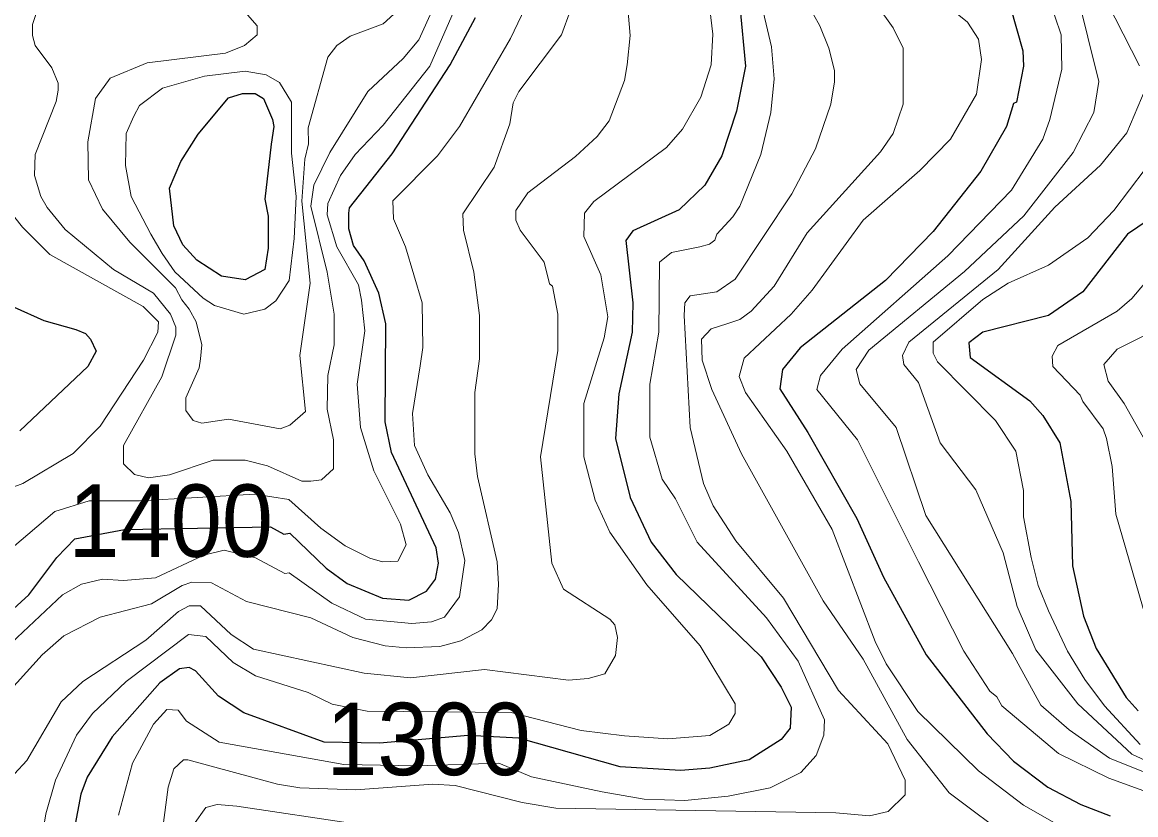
# Model space of a CAD drawing. Extents: x 423 to 448.8, y 7456.3 to 7484.
# Drawn here: x 434.869 to 436.1, y 7473.326 to 7474.202 of the extents above; entities that cross this region are included whole.
import ezdxf
from ezdxf.enums import TextEntityAlignment as Align

# ---------------------------------------------------------------- set-up
doc = ezdxf.new("R2010")
doc.units = 0
doc.header["$LTSCALE"] = 0.032
doc.layers.add('1', color=7, linetype='Continuous', lineweight=25)
doc.layers.add('2', color=7, linetype='Continuous', lineweight=13)
doc.layers.add('61', color=7, linetype='Continuous')

msp = doc.modelspace()

# ---------------------------------------------------------------- linework, layer by layer
at = {"layer": '1'}
for points in [[(435.6623, 7474.2194), (435.6685, 7474.1529), (435.6585, 7474.1034), (435.6422, 7474.0539), (435.6237, 7474.0214), (435.5951, 7473.9943), (435.544, 7473.9711), (435.5363, 7473.9603), (435.544, 7473.8915), (435.5432, 7473.859), (435.5285, 7473.7909), (435.5247, 7473.7414), (435.5409, 7473.6764), (435.5641, 7473.6269), (435.5919, 7473.5913), (435.6856, 7473.5001), (435.708, 7473.4668), (435.7188, 7473.4444), (435.718, 7473.4212), (435.708, 7473.4088), (435.6724, 7473.3864), (435.6291, 7473.3771), (435.5966, 7473.3747), (435.5301, 7473.3786)], [(435.9609, 7474.2194), (435.9748, 7474.1699), (435.9756, 7474.1529), (435.9679, 7474.1134), (435.9647, 7474.1119), (435.957, 7474.0864), (435.9284, 7474.0369), (435.8758, 7473.9703), (435.8232, 7473.9162), (435.7289, 7473.8419), (435.7095, 7473.8179), (435.7064, 7473.7963), (435.7374, 7473.7483), (435.7915, 7473.6532), (435.8209, 7473.5883), (435.8681, 7473.5024), (435.9354, 7473.415), (435.9648, 7473.3848), (436.0027, 7473.3562), (436.039, 7473.3369), (436.0715, 7473.3245)], [(434.8595, 7473.5534), (434.8765, 7473.5689), (434.9074, 7473.6099), (434.9272, 7473.6307), (434.982, 7473.641), (435.1436, 7473.6437), (435.1583, 7473.6358), (435.165, 7473.637), (435.2052, 7473.5983), (435.2284, 7473.5813), (435.2671, 7473.565), (435.2965, 7473.5627), (435.3158, 7473.5728), (435.3259, 7473.5859), (435.329, 7473.6037), (435.3266, 7473.6208), (435.2772, 7473.7259), (435.2702, 7473.76), (435.271, 7473.8683), (435.2632, 7473.9023), (435.247, 7473.9379), (435.2354, 7473.9549), (435.23, 7473.9734), (435.23, 7473.9905), (435.2307, 7473.9966), (435.2779, 7474.0562), (435.3421, 7474.1544), (435.37, 7474.207)], [(436.1705, 7474.0214), (436.0908, 7473.9672), (436.0413, 7473.9038), (436.0035, 7473.8775), (435.9308, 7473.859), (435.9153, 7473.8474), (435.9168, 7473.8311), (435.9826, 7473.7831), (435.9972, 7473.7669), (436.0158, 7473.7368), (436.0282, 7473.6718), (436.0297, 7473.6006), (436.0421, 7473.545), (436.056, 7473.5094), (436.0893, 7473.4552), (436.1024, 7473.4405)], [(434.8603, 7473.8868), (434.8928, 7473.8721), (434.9284, 7473.8621), (434.9391, 7473.8574), (434.9446, 7473.8512), (434.9507, 7473.838), (434.9415, 7473.8211), (434.8665, 7473.7499)], [(435.5301, 7473.3786), (435.4179, 7473.4104), (435.3621, 7473.4133), (435.264, 7473.4046), (435.2027, 7473.406), (435.114, 7473.4382), (435.0861, 7473.4568), (435.0606, 7473.4846), (435.0536, 7473.4884), (435.0428, 7473.4869), (435.0211, 7473.4714), (434.9686, 7473.4119), (434.9407, 7473.367), (434.9338, 7473.3485), (434.9229, 7473.2897), (434.9252, 7473.1892), (434.9229, 7473.1319), (434.9082, 7473.0886), (434.8812, 7473.0584), (434.8556, 7473.0383)]]:
    msp.add_lwpolyline(points, dxfattribs=at)
msp.add_lwpolyline([(435.0636, 7474.0778), (435.097, 7474.1181), (435.1124, 7474.1227), (435.1264, 7474.1227), (435.1356, 7474.1173), (435.1457, 7474.0941), (435.1472, 7474.0864), (435.1442, 7474.0668), (435.1372, 7474.0059), (435.141, 7473.9874), (435.141, 7473.9518), (435.1372, 7473.9285), (435.1155, 7473.9169), (435.0892, 7473.9208), (435.0621, 7473.9386), (435.0467, 7473.9556), (435.0366, 7473.9765), (435.032, 7474.0183), (435.0444, 7474.0477)], close=True, dxfattribs=at)
at = {"layer": '2'}
for points in [[(435.6701, 7474.2906), (435.6972, 7474.1745), (435.7003, 7474.139), (435.6964, 7474.1018), (435.6855, 7474.0554), (435.6623, 7473.9982), (435.6546, 7473.9866), (435.6368, 7473.9673), (435.6346, 7473.9606), (435.6288, 7473.9563), (435.6179, 7473.9534), (435.5865, 7473.9471), (435.5734, 7473.9363), (435.5726, 7473.859), (435.5626, 7473.8017), (435.5626, 7473.743), (435.5765, 7473.6965), (435.5912, 7473.6749), (435.6152, 7473.6269), (435.6917, 7473.5434), (435.7265, 7473.4954), (435.7559, 7473.4304), (435.7551, 7473.4135), (435.7466, 7473.391), (435.7297, 7473.3724), (435.6956, 7473.3554), (435.6492, 7473.3461), (435.6013, 7473.3415), (435.5564, 7473.343), (435.51, 7473.3508), (435.4318, 7473.3676), (435.3958, 7473.3826), (435.3057, 7473.3796), (435.2246, 7473.381), (435.0869, 7473.4057), (435.0506, 7473.4289), (435.0413, 7473.4413), (435.0289, 7473.4421), (435.0142, 7473.4258), (434.991, 7473.3825), (434.9755, 7473.3253)], [(434.8378, 7473.6037), (434.9051, 7473.661), (434.943, 7473.6725), (434.9986, 7473.6726), (435.1262, 7473.6801), (435.1637, 7473.6741), (435.199, 7473.6424), (435.2261, 7473.623), (435.2532, 7473.6091), (435.2671, 7473.6053), (435.2841, 7473.606), (435.2934, 7473.6238), (435.2872, 7473.647), (435.2578, 7473.7058), (435.2431, 7473.7538), (435.2393, 7473.8017), (435.2478, 7473.8605), (435.2439, 7473.8946), (435.2408, 7473.9115), (435.2168, 7473.9533), (435.206, 7473.9889), (435.2068, 7474.0013), (435.2207, 7474.0322), (435.237, 7474.0554), (435.2679, 7474.0879), (435.3197, 7474.1529), (435.3708, 7474.2705)], [(434.8448, 7473.5039), (434.9136, 7473.5689), (434.9345, 7473.5805), (434.9577, 7473.5859), (434.9809, 7473.5844), (435.0165, 7473.5875), (435.0698, 7473.6127), (435.0923, 7473.618), (435.1269, 7473.6097), (435.1592, 7473.5924), (435.1642, 7473.5929), (435.2114, 7473.5596), (435.2486, 7473.5419), (435.2996, 7473.5372), (435.3213, 7473.5388), (435.3359, 7473.5441), (435.3522, 7473.5666), (435.3584, 7473.6068), (435.3514, 7473.6377), (435.3421, 7473.6594), (435.3174, 7473.7012), (435.3027, 7473.7336), (435.3004, 7473.7693), (435.3089, 7473.8218), (435.312, 7473.842), (435.3112, 7473.8915), (435.2926, 7473.9533), (435.2795, 7473.9843), (435.2787, 7474.0044), (435.3282, 7474.0539), (435.3522, 7474.0863), (435.4087, 7474.1838), (435.4373, 7474.2442)], [(435.6268, 7474.2349), (435.6322, 7474.1885), (435.6306, 7474.1544), (435.619, 7474.1189), (435.5989, 7474.0833), (435.5811, 7474.0631), (435.5007, 7474.0036), (435.4906, 7473.9905), (435.4899, 7473.9649), (435.5084, 7473.9224), (435.5162, 7473.876), (435.5123, 7473.8528), (435.4899, 7473.7801), (435.4899, 7473.7213), (435.5023, 7473.6733), (435.5185, 7473.6378), (435.5595, 7473.5797), (435.6183, 7473.5125), (435.6569, 7473.4482), (435.6569, 7473.4374), (435.65, 7473.4258), (435.6291, 7473.4134), (435.5827, 7473.4096), (435.5347, 7473.4127), (435.4868, 7473.4188), (435.4096, 7473.4387), (435.2505, 7473.4403), (435.2115, 7473.4479), (435.1851, 7473.4606), (435.1271, 7473.4792), (435.1024, 7473.4939), (435.0722, 7473.5225), (435.0529, 7473.5248), (434.984, 7473.473), (434.9469, 7473.4374), (434.9291, 7473.4135), (434.9059, 7473.364), (434.8951, 7473.3268), (434.8912, 7473.3021)], [(435.0915, 7474.2403), (435.1286, 7474.1977), (435.1286, 7474.1877), (435.1147, 7474.176), (435.0939, 7474.1676), (435.0072, 7474.1567), (434.9662, 7474.1397), (434.95, 7474.1173), (434.9415, 7474.0694), (434.9422, 7474.0276), (434.9577, 7473.9951), (434.9879, 7473.9587), (435.0385, 7473.9082), (435.0455, 7473.8949), (435.0536, 7473.8845), (435.0614, 7473.8706), (435.0676, 7473.8451), (435.066, 7473.8296), (435.0645, 7473.8195), (435.0498, 7473.7863), (435.0498, 7473.7723), (435.0582, 7473.7615), (435.0676, 7473.7584), (435.097, 7473.763), (435.1542, 7473.7522), (435.165, 7473.7561), (435.182, 7473.7715), (435.1759, 7473.8334), (435.1874, 7473.9131), (435.1783, 7474.0039), (435.1813, 7474.0504), (435.1856, 7474.0674), (435.1851, 7474.0848), (435.2068, 7474.1629), (435.2168, 7474.176), (435.2315, 7474.1861), (435.2679, 7474.2), (435.288, 7474.2178)], [(436.0347, 7474.2345), (436.059, 7474.136), (436.0533, 7474.1018), (436.0305, 7474.0575), (435.9762, 7473.9876), (435.9106, 7473.9262), (435.8049, 7473.8391), (435.7907, 7473.8177), (435.7949, 7473.802), (435.8349, 7473.7535), (435.8677, 7473.6564), (435.9634, 7473.5037), (435.9948, 7473.4466), (436.0262, 7473.4195), (436.0709, 7473.3883), (436.144, 7473.3587)], [(436.0591, 7474.2418), (436.104, 7474.1536)], [(435.5378, 7474.1544), (435.5409, 7474.1869), (435.5378, 7474.2256)], [(435.7188, 7473.8791), (435.742, 7473.9053), (435.7985, 7473.9827), (435.8611, 7474.0376), (435.8951, 7474.0725), (435.9238, 7474.122), (435.9292, 7474.1606), (435.9261, 7474.183), (435.9137, 7474.2016), (435.8782, 7474.231)], [(436.0034, 7474.2294), (436.0174, 7474.1877), (436.0181, 7474.1498), (436.005, 7474.0941), (435.9972, 7474.0725), (435.9624, 7474.016), (435.8921, 7473.9433), (435.7753, 7473.8404), (435.7513, 7473.811), (435.7474, 7473.7956), (435.7923, 7473.7399), (435.8596, 7473.6053), (435.9098, 7473.5063), (435.9385, 7473.4622), (435.9462, 7473.456), (435.9516, 7473.4459), (436.0143, 7473.3933), (436.07, 7473.3662), (436.1288, 7473.3446)], [(434.8355, 7473.4413), (434.8912, 7473.5024), (434.9152, 7473.5233), (434.9554, 7473.5441), (435.0119, 7473.5589), (435.0459, 7473.579), (435.0567, 7473.5828), (435.0784, 7473.5821), (435.1171, 7473.5612), (435.1882, 7473.5434), (435.2346, 7473.5217), (435.2702, 7473.5124), (435.2934, 7473.5101), (435.3306, 7473.5117), (435.3538, 7473.5178), (435.3769, 7473.5302), (435.3878, 7473.5411), (435.394, 7473.5534), (435.3955, 7473.5805), (435.394, 7473.6053), (435.3723, 7473.6996), (435.3692, 7473.7244), (435.3692, 7473.7925), (435.3746, 7473.8296), (435.3746, 7473.8775), (435.3684, 7473.9255), (435.3568, 7473.9719), (435.356, 7473.9897), (435.3908, 7474.0415), (435.4079, 7474.0895), (435.4117, 7474.1127), (435.4179, 7474.125), (435.4651, 7474.1877), (435.4752, 7474.2148)], [(435.3236, 7474.2179), (435.3073, 7474.1823), (435.2903, 7474.1614), (435.2509, 7474.125), (435.2091, 7474.0577), (435.1913, 7474.0214), (435.1882, 7473.9982), (435.206, 7473.9255), (435.2137, 7473.8791), (435.2137, 7473.8451), (435.2068, 7473.811), (435.206, 7473.7739), (435.213, 7473.7399), (435.213, 7473.7081), (435.1998, 7473.6958), (435.1882, 7473.6942), (435.1782, 7473.6942), (435.1403, 7473.7112), (435.1155, 7473.7174), (435.08, 7473.7174), (435.032, 7473.7012), (435.0088, 7473.6981), (434.9933, 7473.7019), (434.9809, 7473.7135), (434.9809, 7473.7337), (435.0235, 7473.8095), (435.0389, 7473.8559), (435.0389, 7473.8644), (435.0328, 7473.8791), (435.0142, 7473.9022), (434.9701, 7473.9285), (434.9167, 7473.9727), (434.8966, 7473.9967), (434.8896, 7474.009), (434.8827, 7474.0322), (434.8835, 7474.0554), (434.9067, 7474.1142), (434.909, 7474.1266), (434.909, 7474.1343), (434.902, 7474.1513), (434.8835, 7474.1761), (434.8804, 7474.1869), (434.8804, 7474.1993), (434.885, 7474.2124)], [(435.7435, 7474.2101), (435.7505, 7474.1978), (435.7606, 7474.173), (435.7668, 7474.1483), (435.7668, 7474.1359), (435.7629, 7474.1111), (435.7459, 7474.0616), (435.7196, 7474.0121), (435.6569, 7473.9178), (435.6368, 7473.9038), (435.6074, 7473.8992), (435.6013, 7473.8914), (435.6005, 7473.8775), (435.6074, 7473.7538), (435.6221, 7473.6919), (435.6329, 7473.6672), (435.6577, 7473.6285), (435.7103, 7473.565), (435.7714, 7473.463), (435.8256, 7473.4041), (435.8449, 7473.364), (435.8449, 7473.3477), (435.8263, 7473.3291), (435.8055, 7473.3245), (435.7683, 7473.3276), (435.4589, 7473.333), (435.4218, 7473.3392), (435.3476, 7473.3578), (435.3228, 7473.3593), (435.2377, 7473.3531), (435.1759, 7473.3554), (435.1511, 7473.3593), (435.0521, 7473.3864), (435.0475, 7473.3864), (435.0366, 7473.3763), (435.0304, 7473.3562), (435.0188, 7473.2696)], [(435.8139, 7474.2202), (435.8317, 7474.1954)], [(435.8317, 7474.1954), (435.8426, 7474.173), (435.8426, 7474.1111), (435.8317, 7474.0786), (435.8178, 7474.0585), (435.7366, 7473.9688), (435.7002, 7473.91), (435.6747, 7473.8822), (435.6623, 7473.8729), (435.6477, 7473.8683), (435.6307, 7473.8628), (435.6198, 7473.8512), (435.6206, 7473.828), (435.6314, 7473.7956), (435.6639, 7473.7244), (435.7544, 7473.562), (435.7985, 7473.4977), (435.8472, 7473.4088), (435.8936, 7473.35), (435.9655, 7473.2959), (436.0189, 7473.2742), (436.0901, 7473.2549), (436.2138, 7473.2371)], [(434.8193, 7473.3268), (434.8742, 7473.3856), (434.9121, 7473.4506), (434.936, 7473.473), (435.0057, 7473.5186), (435.042, 7473.5503), (435.0536, 7473.5565), (435.066, 7473.5565), (435.1001, 7473.5248), (435.1248, 7473.5086), (435.247, 7473.4823), (435.2981, 7473.4768), (435.3801, 7473.4861), (435.4729, 7473.4745), (435.4945, 7473.4761), (435.513, 7473.4815), (435.5247, 7473.5016), (435.527, 7473.5217), (435.5239, 7473.5356), (435.5185, 7473.5418), (435.4674, 7473.5751), (435.4543, 7473.6037), (435.4419, 7473.7213), (435.4612, 7473.8389), (435.4612, 7473.8791), (435.455, 7473.91), (435.452, 7473.9123), (435.4458, 7473.9363), (435.4195, 7473.9719), (435.4148, 7473.9827), (435.4148, 7473.9936), (435.428, 7474.0129), (435.4806, 7474.0531), (435.5045, 7474.0755), (435.5177, 7474.0925), (435.5347, 7474.1374), (435.5378, 7474.1544)], [(436.1102, 7474.1273), (436.0901, 7474.0794), (436.0607, 7474.0438), (436.0104, 7473.9974), (435.9477, 7473.9285), (435.8488, 7473.8481), (435.8418, 7473.8334), (435.8433, 7473.8234), (435.8596, 7473.8033), (435.8836, 7473.7368), (435.923, 7473.6849), (435.9532, 7473.6153), (435.9686, 7473.5558), (435.9895, 7473.5078), (436.0359, 7473.4482), (436.0956, 7473.3925)], [(436.1102, 7474.0392), (436.0754, 7473.9936), (436.0467, 7473.9634), (436.0035, 7473.9332), (435.9586, 7473.9131), (435.9308, 7473.8953), (435.8758, 7473.8481), (435.8758, 7473.8358), (435.8805, 7473.8264), (435.9447, 7473.7615), (435.9671, 7473.7275), (435.9756, 7473.6842), (435.9756, 7473.6548), (435.9841, 7473.6099), (435.9918, 7473.579), (436.0035, 7473.5511), (436.0243, 7473.5063), (436.0436, 7473.4753), (436.0653, 7473.4459)], [(434.8525, 7473.9966), (434.8695, 7473.975), (434.8997, 7473.9448), (435.0026, 7473.8876), (435.0196, 7473.8706), (435.0188, 7473.859), (435.0033, 7473.828), (434.9554, 7473.7553), (434.9253, 7473.7251), (434.8696, 7473.6919), (434.7969, 7473.6648)], [(436.1574, 7473.9696), (436.0955, 7473.8961), (436.0792, 7473.8822), (436.0135, 7473.8443), (436.0073, 7473.8326), (436.0081, 7473.821), (436.0382, 7473.7893), (436.0413, 7473.7824), (436.0638, 7473.7522), (436.0676, 7473.7414), (436.0738, 7473.7105), (436.0777, 7473.6579), (436.1295, 7473.48)], [(436.1117, 7473.2765), (436.0127, 7473.3152), (435.9756, 7473.3361), (435.9261, 7473.374), (435.8588, 7473.4398), (435.824, 7473.4924), (435.8116, 7473.5171), (435.7644, 7473.6409), (435.7141, 7473.7275), (435.6685, 7473.7925), (435.6616, 7473.8102), (435.667, 7473.8303), (435.7188, 7473.8791)], [(436.1117, 7473.8566), (436.0793, 7473.8404), (436.0645, 7473.8234), (436.0692, 7473.8048), (436.087, 7473.7801), (436.1078, 7473.743)], [(436.0653, 7473.4459), (436.1048, 7473.4034)], [(436.0956, 7473.3925), (436.1424, 7473.3709)], [(435.2393, 7473.3152), (435.1062, 7473.3353), (435.0846, 7473.3369), (435.0722, 7473.3338), (435.0583, 7473.3145)]]:
    msp.add_lwpolyline(points, dxfattribs=at)
msp.add_lwpolyline([(434.9925, 7474.0979), (434.9987, 7474.1096), (435.0243, 7474.1289), (435.0707, 7474.142), (435.1155, 7474.1475), (435.1387, 7474.1436), (435.1534, 7474.1351), (435.1666, 7474.1134), (435.1666, 7474.057), (435.172, 7474.009), (435.1697, 7473.9626), (435.1642, 7473.9162), (435.1495, 7473.8938), (435.1372, 7473.8845), (435.114, 7473.8791), (435.0815, 7473.8884), (435.0691, 7473.8968), (435.0376, 7473.9256), (435.0239, 7473.9459), (435.0111, 7473.9673), (434.9894, 7474.009), (434.9832, 7474.0431), (434.984, 7474.0786)], close=True, dxfattribs=at)

# ---------------------------------------------------------------- texts
at = {"layer": '61', "width": 0.95}
for s, p in [('1400', (435.0332, 7473.6107)), ('1300', (435.3181, 7473.3694))]:
    msp.add_text(s, height=0.08, dxfattribs=at).set_placement(p, align=Align.CENTER)

doc.saveas('drawing.dxf')
